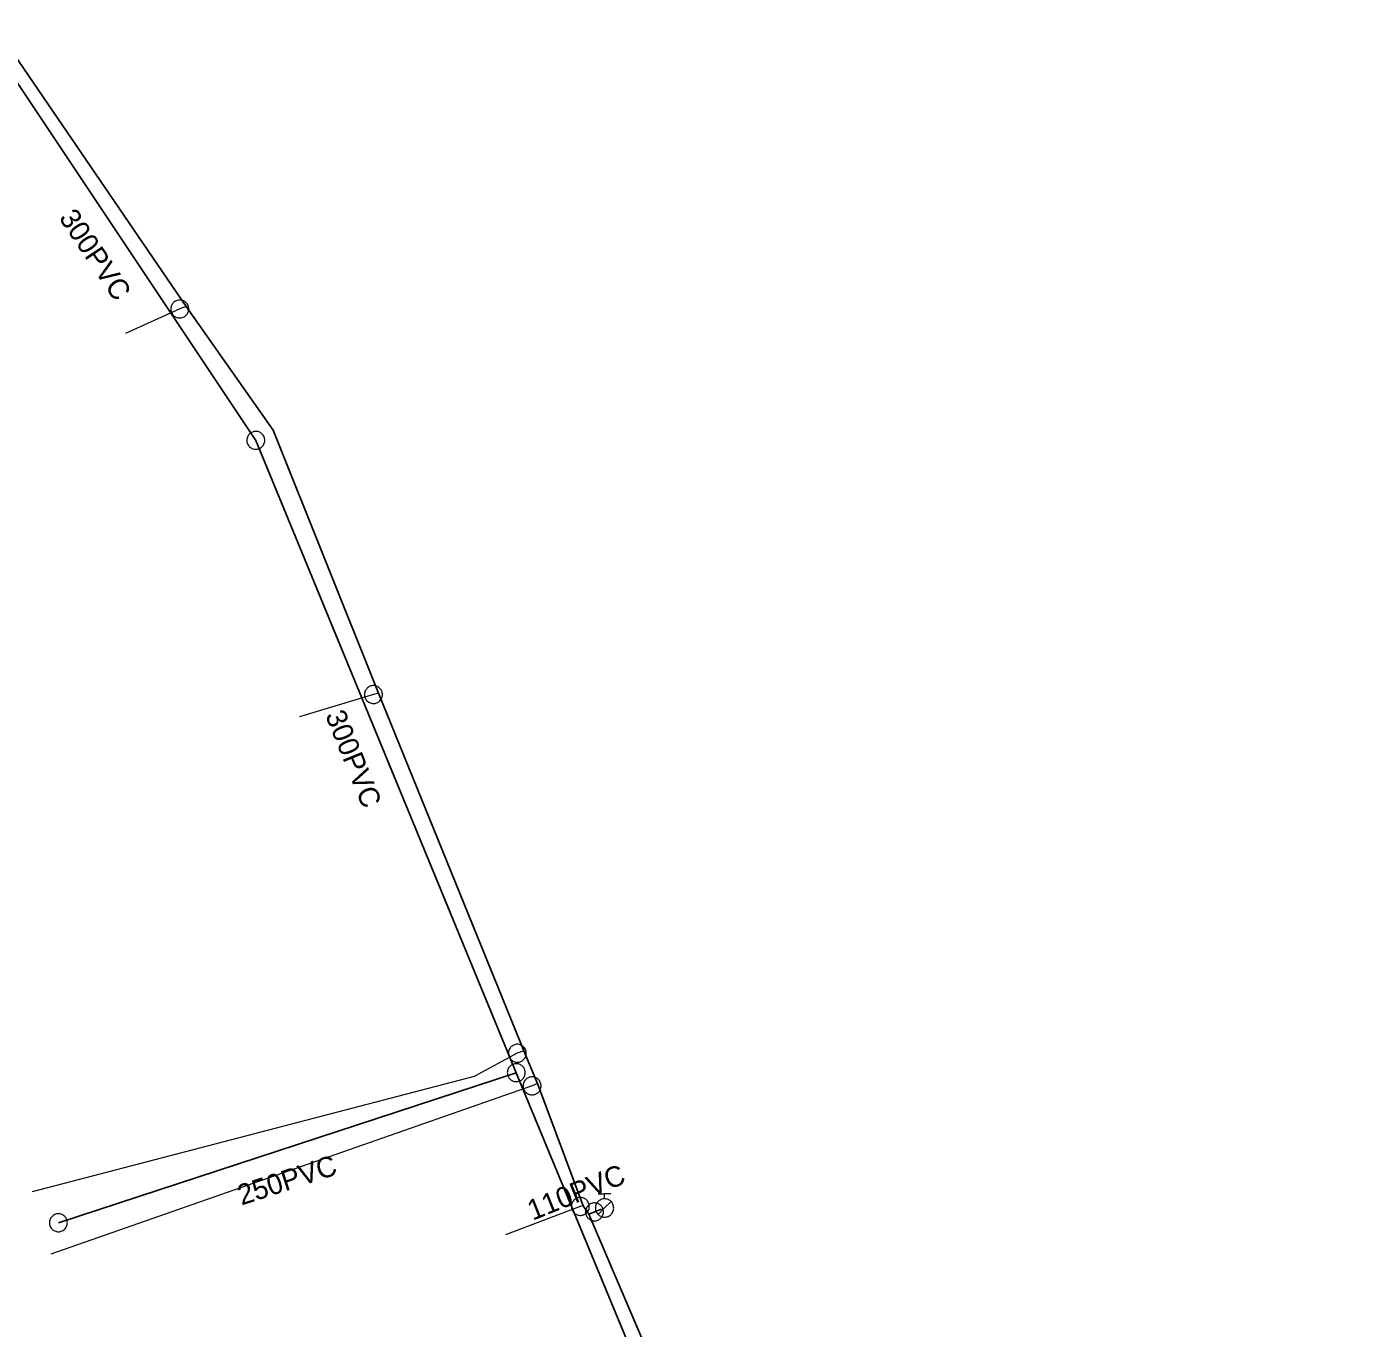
# Model space of a CAD drawing. Extents: x -741806 to -738704, y -1059275 to -1055387.
# Drawn here: x -740539.1 to -740474.2, y -1057228.9 to -1057165.3 of the extents above; entities that cross this region are included whole.
import ezdxf

# ---------------------------------------------------------------- set-up
doc = ezdxf.new("R2010")
doc.units = 0
doc.header["$LTSCALE"] = 0.4
for name, color, linetype, lineweight in [('2', 7, 'Continuous', 25), ('21', 7, 'Continuous', 13), ('3', 7, 'Continuous', 13), ('50', 7, 'Continuous', 13), ('51', 7, 'Continuous', 13), ('52', 7, 'Continuous', 25)]:
    doc.layers.add(name, color=color, linetype=linetype, lineweight=lineweight)
doc.layers.add('5', color=7, linetype='Continuous')
doc.layers.add('53', color=7, linetype='Continuous')

msp = doc.modelspace()

# ---------------------------------------------------------------- linework, layer by layer
at = {"layer": '2'}
for p, q in [((-740527.879, -1057185.53), (-740540.52, -1057166.61)), ((-740495.51, -1057263.81), (-740515.17, -1057216.379))]:
    msp.add_line(p, q, dxfattribs=at)
msp.add_lwpolyline([(-740537.51, -1057223.7), (-740515.17, -1057216.379), (-740527.879, -1057185.53)], dxfattribs=at)
at = {"layer": '21'}
for points in [[(-740531.278, -1057178.995), (-740531.589, -1057179.122), (-740534.241, -1057180.321)], [(-740521.886, -1057197.858), (-740522.138, -1057197.932), (-740525.745, -1057199.014)], [(-740514.802, -1057215.317), (-740515.118, -1057215.431), (-740517.23, -1057216.57), (-740538.793, -1057222.199)], [(-740514.131, -1057216.899), (-740514.397, -1057217.022), (-740537.883, -1057225.233)], [(-740511.897, -1057222.875), (-740512.046, -1057222.905), (-740515.688, -1057224.298)]]:
    msp.add_lwpolyline(points, dxfattribs=at)
at = {"layer": '3'}
for points in [[(-740528.045, -1057185.124), (-740528.085, -1057185.144), (-740528.124, -1057185.168), (-740528.161, -1057185.196), (-740528.194, -1057185.227), (-740528.224, -1057185.262), (-740528.251, -1057185.3), (-740528.272, -1057185.34), (-740528.29, -1057185.382), (-740528.302, -1057185.426), (-740528.311, -1057185.471), (-740528.315, -1057185.517), (-740528.314, -1057185.563), (-740528.308, -1057185.608), (-740528.298, -1057185.652), (-740528.282, -1057185.696), (-740528.263, -1057185.738), (-740528.238, -1057185.776), (-740528.211, -1057185.813), (-740528.179, -1057185.846), (-740528.144, -1057185.876), (-740528.107, -1057185.901), (-740528.067, -1057185.923), (-740528.024, -1057185.941), (-740527.981, -1057185.955), (-740527.935, -1057185.963), (-740527.89, -1057185.966), (-740527.844, -1057185.965), (-740527.798, -1057185.959), (-740527.754, -1057185.949), (-740527.711, -1057185.933), (-740527.67, -1057185.914), (-740527.631, -1057185.89), (-740527.594, -1057185.862), (-740527.561, -1057185.83), (-740527.531, -1057185.796), (-740527.505, -1057185.758), (-740527.483, -1057185.718), (-740527.465, -1057185.675), (-740527.453, -1057185.632), (-740527.444, -1057185.587), (-740527.44, -1057185.542), (-740527.441, -1057185.495), (-740527.447, -1057185.45), (-740527.457, -1057185.406), (-740527.473, -1057185.362), (-740527.492, -1057185.321), (-740527.516, -1057185.282), (-740527.544, -1057185.246), (-740527.576, -1057185.212), (-740527.611, -1057185.182), (-740527.649, -1057185.157), (-740527.688, -1057185.134), (-740527.731, -1057185.117), (-740527.774, -1057185.104), (-740527.82, -1057185.095), (-740527.866, -1057185.092), (-740527.911, -1057185.093), (-740527.957, -1057185.099), (-740528.001, -1057185.11), (-740528.044, -1057185.124)], [(-740515.337, -1057215.974), (-740515.377, -1057215.994), (-740515.416, -1057216.017), (-740515.453, -1057216.046), (-740515.486, -1057216.077), (-740515.516, -1057216.112), (-740515.542, -1057216.15), (-740515.563, -1057216.19), (-740515.581, -1057216.232), (-740515.594, -1057216.276), (-740515.602, -1057216.321), (-740515.606, -1057216.367), (-740515.605, -1057216.413), (-740515.598, -1057216.458), (-740515.588, -1057216.502), (-740515.573, -1057216.546), (-740515.553, -1057216.587), (-740515.529, -1057216.626), (-740515.502, -1057216.662), (-740515.469, -1057216.696), (-740515.434, -1057216.725), (-740515.397, -1057216.751), (-740515.357, -1057216.773), (-740515.314, -1057216.79), (-740515.271, -1057216.804), (-740515.225, -1057216.812), (-740515.18, -1057216.815), (-740515.134, -1057216.814), (-740515.088, -1057216.808), (-740515.044, -1057216.797), (-740515.001, -1057216.782), (-740514.96, -1057216.763), (-740514.921, -1057216.739), (-740514.884, -1057216.711), (-740514.851, -1057216.678), (-740514.822, -1057216.645), (-740514.795, -1057216.607), (-740514.774, -1057216.566), (-740514.756, -1057216.523), (-740514.744, -1057216.48), (-740514.735, -1057216.435), (-740514.731, -1057216.39), (-740514.732, -1057216.343), (-740514.738, -1057216.298), (-740514.749, -1057216.254), (-740514.764, -1057216.211), (-740514.784, -1057216.169), (-740514.808, -1057216.13), (-740514.836, -1057216.094), (-740514.868, -1057216.061), (-740514.903, -1057216.031), (-740514.94, -1057216.005), (-740514.98, -1057215.983), (-740515.023, -1057215.966), (-740515.066, -1057215.952), (-740515.112, -1057215.944), (-740515.158, -1057215.941), (-740515.203, -1057215.942), (-740515.249, -1057215.948), (-740515.293, -1057215.959), (-740515.336, -1057215.973)], [(-740537.093, -1057223.564), (-740537.11, -1057223.522), (-740537.131, -1057223.481), (-740537.156, -1057223.442), (-740537.184, -1057223.407), (-740537.217, -1057223.375), (-740537.253, -1057223.346), (-740537.291, -1057223.321), (-740537.332, -1057223.3), (-740537.375, -1057223.285), (-740537.419, -1057223.273), (-740537.464, -1057223.265), (-740537.511, -1057223.263), (-740537.556, -1057223.266), (-740537.601, -1057223.272), (-740537.645, -1057223.285), (-740537.689, -1057223.301), (-740537.729, -1057223.323), (-740537.767, -1057223.347), (-740537.803, -1057223.376), (-740537.835, -1057223.409), (-740537.863, -1057223.445), (-740537.888, -1057223.482), (-740537.909, -1057223.524), (-740537.926, -1057223.566), (-740537.937, -1057223.611), (-740537.944, -1057223.656), (-740537.947, -1057223.701), (-740537.944, -1057223.748), (-740537.937, -1057223.793), (-740537.924, -1057223.837), (-740537.908, -1057223.879), (-740537.888, -1057223.92), (-740537.862, -1057223.959), (-740537.833, -1057223.994), (-740537.801, -1057224.026), (-740537.765, -1057224.055), (-740537.727, -1057224.08), (-740537.685, -1057224.101), (-740537.643, -1057224.116), (-740537.599, -1057224.128), (-740537.554, -1057224.136), (-740537.508, -1057224.138), (-740537.462, -1057224.136), (-740537.417, -1057224.129), (-740537.373, -1057224.116), (-740537.33, -1057224.1), (-740537.289, -1057224.079), (-740537.251, -1057224.054), (-740537.216, -1057224.025), (-740537.183, -1057223.992), (-740537.155, -1057223.956), (-740537.129, -1057223.919), (-740537.109, -1057223.877), (-740537.093, -1057223.835), (-740537.081, -1057223.79), (-740537.074, -1057223.745), (-740537.072, -1057223.7), (-740537.074, -1057223.653), (-740537.082, -1057223.608), (-740537.093, -1057223.565)]]:
    msp.add_lwpolyline(points, dxfattribs=at)
at = {"layer": '50'}
for p, q in [((-740511.167, -1057222.282), (-740510.859, -1057222.282)), ((-740510.859, -1057222.533), (-740510.859, -1057222.282)), ((-740510.552, -1057222.282), (-740510.859, -1057222.282)), ((-740510.859, -1057222.98), (-740510.543, -1057222.668)), ((-740510.859, -1057222.98), (-740511.176, -1057223.297))]:
    msp.add_line(p, q, dxfattribs=at)
msp.add_lwpolyline([(-740510.415, -1057222.984), (-740510.417, -1057222.935), (-740510.422, -1057222.889), (-740510.435, -1057222.843), (-740510.452, -1057222.8), (-740510.471, -1057222.76), (-740510.498, -1057222.719), (-740510.527, -1057222.684), (-740510.56, -1057222.649), (-740510.595, -1057222.619), (-740510.635, -1057222.595), (-740510.676, -1057222.573), (-740510.719, -1057222.554), (-740510.765, -1057222.544), (-740510.811, -1057222.536), (-740510.857, -1057222.533), (-740510.903, -1057222.536), (-740510.948, -1057222.541), (-740510.994, -1057222.554), (-740511.038, -1057222.571), (-740511.081, -1057222.592), (-740511.119, -1057222.617), (-740511.156, -1057222.646), (-740511.189, -1057222.679), (-740511.218, -1057222.714), (-740511.245, -1057222.754), (-740511.267, -1057222.795), (-740511.283, -1057222.838), (-740511.297, -1057222.884), (-740511.302, -1057222.93), (-740511.309, -1057222.976), (-740511.306, -1057223.024), (-740511.298, -1057223.07), (-740511.287, -1057223.113), (-740511.271, -1057223.159), (-740511.249, -1057223.2), (-740511.225, -1057223.24), (-740511.195, -1057223.275), (-740511.163, -1057223.31), (-740511.125, -1057223.34), (-740511.087, -1057223.364), (-740511.044, -1057223.386), (-740511.001, -1057223.402), (-740510.958, -1057223.416), (-740510.909, -1057223.424), (-740510.863, -1057223.427), (-740510.817, -1057223.424), (-740510.771, -1057223.416), (-740510.725, -1057223.405), (-740510.682, -1057223.389), (-740510.639, -1057223.367), (-740510.601, -1057223.343), (-740510.563, -1057223.313), (-740510.531, -1057223.281), (-740510.501, -1057223.246), (-740510.477, -1057223.205), (-740510.453, -1057223.165), (-740510.436, -1057223.121), (-740510.426, -1057223.076), (-740510.418, -1057223.03)], close=True, dxfattribs=at)
at = {"layer": '51'}
for points in [[(-740531.834, -1057178.76), (-740531.871, -1057178.787), (-740531.904, -1057178.818), (-740531.934, -1057178.854), (-740531.96, -1057178.891), (-740531.982, -1057178.931), (-740532, -1057178.974), (-740532.012, -1057179.017), (-740532.022, -1057179.062), (-740532.025, -1057179.108), (-740532.024, -1057179.153), (-740532.018, -1057179.199), (-740532.008, -1057179.244), (-740531.993, -1057179.287), (-740531.973, -1057179.328), (-740531.949, -1057179.368), (-740531.921, -1057179.404), (-740531.89, -1057179.438), (-740531.856, -1057179.467), (-740531.817, -1057179.493), (-740531.777, -1057179.515), (-740531.735, -1057179.533), (-740531.691, -1057179.546), (-740531.646, -1057179.554), (-740531.601, -1057179.558), (-740531.554, -1057179.557), (-740531.509, -1057179.551), (-740531.465, -1057179.541), (-740531.421, -1057179.525), (-740531.38, -1057179.506), (-740531.34, -1057179.482), (-740531.305, -1057179.455), (-740531.272, -1057179.423), (-740531.241, -1057179.388), (-740531.216, -1057179.351), (-740531.194, -1057179.311), (-740531.175, -1057179.268), (-740531.163, -1057179.224), (-740531.154, -1057179.179), (-740531.151, -1057179.134), (-740531.152, -1057179.088), (-740531.157, -1057179.043), (-740531.168, -1057178.998), (-740531.183, -1057178.955), (-740531.202, -1057178.913), (-740531.226, -1057178.874), (-740531.254, -1057178.837), (-740531.286, -1057178.805), (-740531.32, -1057178.775), (-740531.358, -1057178.749), (-740531.399, -1057178.727), (-740531.441, -1057178.709), (-740531.484, -1057178.695), (-740531.529, -1057178.688), (-740531.575, -1057178.683), (-740531.621, -1057178.685), (-740531.667, -1057178.69), (-740531.71, -1057178.701), (-740531.754, -1057178.716), (-740531.795, -1057178.736)], [(-740512.475, -1057222.987), (-740512.464, -1057223.031), (-740512.449, -1057223.074), (-740512.428, -1057223.116), (-740512.404, -1057223.154), (-740512.376, -1057223.19), (-740512.344, -1057223.224), (-740512.309, -1057223.253), (-740512.271, -1057223.279), (-740512.23, -1057223.3), (-740512.188, -1057223.317), (-740512.144, -1057223.33), (-740512.099, -1057223.338), (-740512.053, -1057223.342), (-740512.008, -1057223.34), (-740511.962, -1057223.333), (-740511.917, -1057223.322), (-740511.875, -1057223.307), (-740511.834, -1057223.287), (-740511.795, -1057223.262), (-740511.758, -1057223.233), (-740511.726, -1057223.201), (-740511.696, -1057223.167), (-740511.671, -1057223.129), (-740511.649, -1057223.089), (-740511.632, -1057223.046), (-740511.619, -1057223.001), (-740511.611, -1057222.957), (-740511.608, -1057222.911), (-740511.61, -1057222.865), (-740511.616, -1057222.819), (-740511.627, -1057222.776), (-740511.643, -1057222.733), (-740511.663, -1057222.691), (-740511.687, -1057222.653), (-740511.715, -1057222.617), (-740511.747, -1057222.583), (-740511.783, -1057222.554), (-740511.82, -1057222.528), (-740511.861, -1057222.507), (-740511.903, -1057222.49), (-740511.947, -1057222.477), (-740511.993, -1057222.469), (-740512.038, -1057222.467), (-740512.084, -1057222.467), (-740512.129, -1057222.474), (-740512.174, -1057222.485), (-740512.217, -1057222.501), (-740512.258, -1057222.52), (-740512.297, -1057222.545), (-740512.333, -1057222.574), (-740512.365, -1057222.606), (-740512.395, -1057222.64), (-740512.421, -1057222.678), (-740512.442, -1057222.718), (-740512.459, -1057222.761), (-740512.472, -1057222.806), (-740512.48, -1057222.85), (-740512.483, -1057222.896), (-740512.481, -1057222.942)]]:
    msp.add_lwpolyline(points, close=True, dxfattribs=at)
for points in [[(-740522.557, -1057198.054), (-740522.542, -1057198.097), (-740522.523, -1057198.138), (-740522.499, -1057198.178), (-740522.472, -1057198.214), (-740522.44, -1057198.247), (-740522.405, -1057198.277), (-740522.367, -1057198.303), (-740522.327, -1057198.325), (-740522.285, -1057198.342), (-740522.241, -1057198.355), (-740522.196, -1057198.364), (-740522.15, -1057198.368), (-740522.104, -1057198.367), (-740522.059, -1057198.361), (-740522.015, -1057198.35), (-740521.971, -1057198.335), (-740521.93, -1057198.316), (-740521.891, -1057198.292), (-740521.854, -1057198.264), (-740521.821, -1057198.232), (-740521.792, -1057198.197), (-740521.765, -1057198.16), (-740521.744, -1057198.12), (-740521.726, -1057198.078), (-740521.713, -1057198.033), (-740521.704, -1057197.988), (-740521.7, -1057197.943), (-740521.702, -1057197.897), (-740521.708, -1057197.852), (-740521.718, -1057197.807), (-740521.733, -1057197.764), (-740521.753, -1057197.723), (-740521.777, -1057197.683), (-740521.804, -1057197.648), (-740521.836, -1057197.614), (-740521.871, -1057197.584), (-740521.908, -1057197.558), (-740521.948, -1057197.536), (-740521.991, -1057197.519), (-740522.034, -1057197.506), (-740522.08, -1057197.497), (-740522.126, -1057197.493), (-740522.171, -1057197.495), (-740522.216, -1057197.5), (-740522.261, -1057197.511), (-740522.305, -1057197.526), (-740522.346, -1057197.546), (-740522.385, -1057197.569), (-740522.421, -1057197.597), (-740522.455, -1057197.629), (-740522.484, -1057197.664), (-740522.511, -1057197.701), (-740522.532, -1057197.741), (-740522.55, -1057197.783), (-740522.563, -1057197.828), (-740522.572, -1057197.873), (-740522.575, -1057197.918), (-740522.574, -1057197.964), (-740522.568, -1057198.009), (-740522.557, -1057198.053)], [(-740514.681, -1057215.431), (-740514.683, -1057215.386), (-740514.69, -1057215.341), (-740514.702, -1057215.296), (-740514.718, -1057215.254), (-740514.739, -1057215.213), (-740514.764, -1057215.174), (-740514.793, -1057215.139), (-740514.825, -1057215.106), (-740514.861, -1057215.078), (-740514.899, -1057215.053), (-740514.94, -1057215.032), (-740514.983, -1057215.015), (-740515.027, -1057215.003), (-740515.072, -1057214.996), (-740515.118, -1057214.994), (-740515.164, -1057214.996), (-740515.209, -1057215.003), (-740515.253, -1057215.015), (-740515.296, -1057215.032), (-740515.337, -1057215.053), (-740515.375, -1057215.078), (-740515.411, -1057215.106), (-740515.443, -1057215.139), (-740515.472, -1057215.174), (-740515.497, -1057215.213), (-740515.518, -1057215.254), (-740515.534, -1057215.296), (-740515.546, -1057215.341), (-740515.553, -1057215.386), (-740515.556, -1057215.432), (-740515.553, -1057215.477), (-740515.546, -1057215.522), (-740515.534, -1057215.567), (-740515.518, -1057215.609), (-740515.497, -1057215.65), (-740515.472, -1057215.689), (-740515.443, -1057215.724), (-740515.411, -1057215.757), (-740515.375, -1057215.785), (-740515.337, -1057215.81), (-740515.296, -1057215.831), (-740515.253, -1057215.848), (-740515.209, -1057215.859), (-740515.164, -1057215.867), (-740515.118, -1057215.869), (-740515.072, -1057215.867), (-740515.027, -1057215.859), (-740514.983, -1057215.848), (-740514.94, -1057215.831), (-740514.899, -1057215.81), (-740514.861, -1057215.785), (-740514.825, -1057215.757), (-740514.793, -1057215.724), (-740514.764, -1057215.689), (-740514.739, -1057215.65), (-740514.718, -1057215.609), (-740514.702, -1057215.567), (-740514.69, -1057215.522), (-740514.683, -1057215.477), (-740514.681, -1057215.432)], [(-740513.96, -1057217.022), (-740513.962, -1057216.977), (-740513.969, -1057216.932), (-740513.981, -1057216.887), (-740513.997, -1057216.845), (-740514.018, -1057216.804), (-740514.043, -1057216.765), (-740514.072, -1057216.73), (-740514.104, -1057216.697), (-740514.14, -1057216.669), (-740514.178, -1057216.644), (-740514.219, -1057216.623), (-740514.262, -1057216.606), (-740514.306, -1057216.594), (-740514.351, -1057216.587), (-740514.397, -1057216.585), (-740514.443, -1057216.587), (-740514.488, -1057216.594), (-740514.532, -1057216.606), (-740514.575, -1057216.623), (-740514.616, -1057216.644), (-740514.654, -1057216.669), (-740514.69, -1057216.697), (-740514.722, -1057216.73), (-740514.751, -1057216.765), (-740514.776, -1057216.804), (-740514.797, -1057216.845), (-740514.813, -1057216.887), (-740514.825, -1057216.932), (-740514.832, -1057216.977), (-740514.835, -1057217.023), (-740514.832, -1057217.068), (-740514.825, -1057217.113), (-740514.813, -1057217.158), (-740514.797, -1057217.2), (-740514.776, -1057217.241), (-740514.751, -1057217.28), (-740514.722, -1057217.315), (-740514.69, -1057217.348), (-740514.654, -1057217.376), (-740514.616, -1057217.401), (-740514.575, -1057217.422), (-740514.532, -1057217.439), (-740514.488, -1057217.45), (-740514.443, -1057217.458), (-740514.397, -1057217.46), (-740514.351, -1057217.458), (-740514.306, -1057217.45), (-740514.262, -1057217.439), (-740514.219, -1057217.422), (-740514.178, -1057217.401), (-740514.14, -1057217.376), (-740514.104, -1057217.348), (-740514.072, -1057217.315), (-740514.043, -1057217.28), (-740514.018, -1057217.241), (-740513.997, -1057217.2), (-740513.981, -1057217.158), (-740513.969, -1057217.113), (-740513.962, -1057217.068), (-740513.96, -1057217.023)], [(-740510.948, -1057223.005), (-740510.967, -1057222.964), (-740510.99, -1057222.925), (-740511.018, -1057222.888), (-740511.049, -1057222.855), (-740511.084, -1057222.825), (-740511.122, -1057222.798), (-740511.162, -1057222.777), (-740511.204, -1057222.758), (-740511.248, -1057222.746), (-740511.292, -1057222.737), (-740511.338, -1057222.733), (-740511.385, -1057222.734), (-740511.43, -1057222.739), (-740511.474, -1057222.75), (-740511.517, -1057222.765), (-740511.559, -1057222.785), (-740511.598, -1057222.808), (-740511.634, -1057222.836), (-740511.668, -1057222.868), (-740511.698, -1057222.903), (-740511.724, -1057222.94), (-740511.746, -1057222.98), (-740511.764, -1057223.022), (-740511.777, -1057223.066), (-740511.786, -1057223.111), (-740511.79, -1057223.157), (-740511.788, -1057223.202), (-740511.783, -1057223.248), (-740511.772, -1057223.293), (-740511.757, -1057223.336), (-740511.738, -1057223.377), (-740511.714, -1057223.416), (-740511.686, -1057223.453), (-740511.655, -1057223.486), (-740511.62, -1057223.516), (-740511.583, -1057223.543), (-740511.542, -1057223.564), (-740511.5, -1057223.583), (-740511.456, -1057223.595), (-740511.412, -1057223.604), (-740511.366, -1057223.608), (-740511.32, -1057223.607), (-740511.275, -1057223.601), (-740511.23, -1057223.591), (-740511.187, -1057223.575), (-740511.145, -1057223.556), (-740511.106, -1057223.532), (-740511.07, -1057223.505), (-740511.036, -1057223.473), (-740511.006, -1057223.438), (-740510.981, -1057223.401), (-740510.958, -1057223.361), (-740510.941, -1057223.318), (-740510.927, -1057223.275), (-740510.919, -1057223.23), (-740510.915, -1057223.184), (-740510.916, -1057223.139), (-740510.922, -1057223.092), (-740510.932, -1057223.048), (-740510.947, -1057223.006)]]:
    msp.add_lwpolyline(points, dxfattribs=at)
at = {"layer": '52'}
msp.add_line((-740511.625, -1057223.281), (-740511.01, -1057223.03), dxfattribs=at)
msp.add_lwpolyline([(-740474.177, -1057312.86), (-740490.353, -1057275.203), (-740494.495, -1057264.561), (-740494.815, -1057263.44), (-740495.346, -1057262.56), (-740501.754, -1057246.385), (-740511.625, -1057223.281), (-740511.897, -1057222.875), (-740514.131, -1057216.899), (-740514.802, -1057215.317), (-740521.886, -1057197.858), (-740527.024, -1057185.034), (-740531.278, -1057178.995), (-740539.423, -1057167.064), (-740549.234, -1057153.017), (-740552.577, -1057147.45), (-740559.561, -1057135.74), (-740565.054, -1057123.703), (-740568.379, -1057115.976), (-740572.934, -1057106.685), (-740576.155, -1057098.614), (-740576.807, -1057097.32)], dxfattribs=at)

# ---------------------------------------------------------------- texts
at = {"layer": '5'}
for s, rotation, p in [('300PVC', 304, (-740537.517, -1057174.678)), ('300PVC', 292, (-740524.503, -1057198.936)), ('250PVC', 18, (-740528.572, -1057222.86))]:
    msp.add_text(s, height=1, rotation=rotation, dxfattribs=at).set_placement(p)
at = {"layer": '53'}
msp.add_text('110PVC', height=1, rotation=22, dxfattribs=at).set_placement((-740514.372, -1057223.607))

doc.saveas('drawing.dxf')
